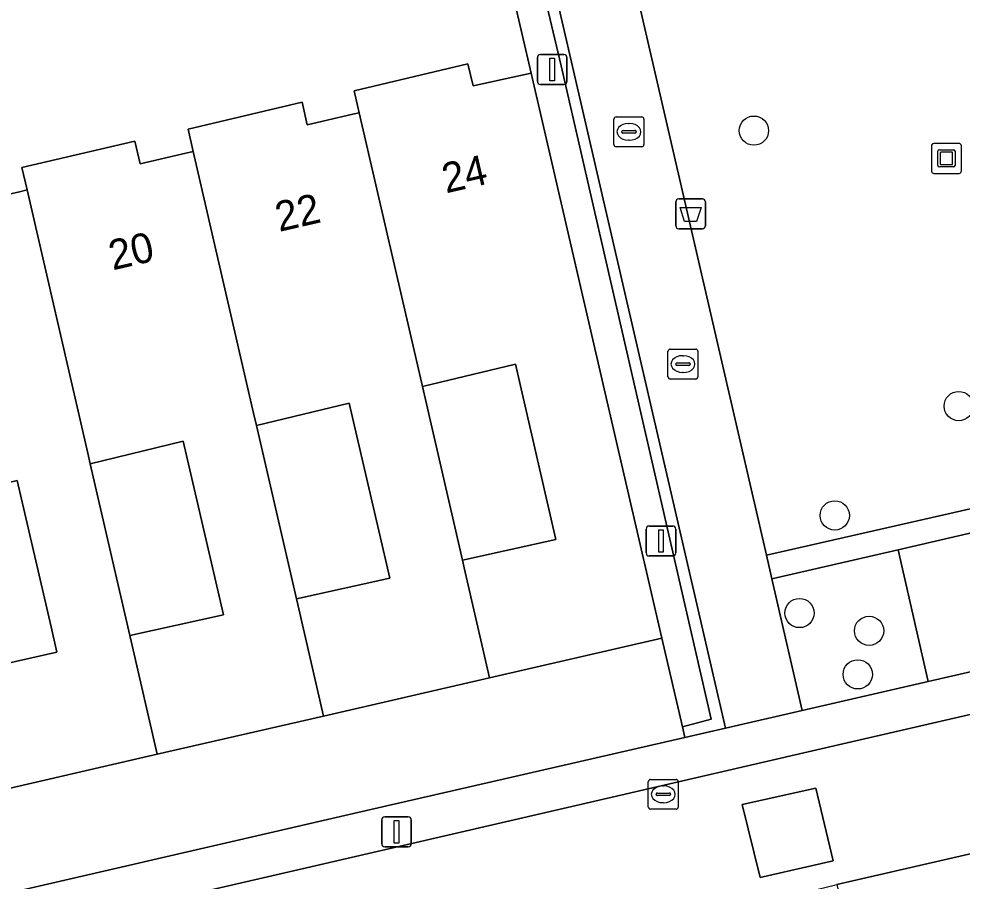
# Model space of a CAD drawing. Extents: x 156412 to 157779, y 382335 to 383768.
# Drawn here: x 156778.51 to 156810.03, y 382711.6 to 382740.43 of the extents above; entities that cross this region are included whole.
import ezdxf

# ---------------------------------------------------------------- set-up
doc = ezdxf.new("R2010")
doc.units = 0
for name, color, linetype in [('IMGEO_Afvalbak', 7, 'Continuous'), ('IMGEO_Boom', 7, 'Continuous'), ('IMGEO_Erf', 7, 'Continuous'), ('IMGEO_Groenvoorziening', 7, 'Continuous'), ('IMGEO_Haag', 7, 'Continuous'), ('IMGEO_Kolk', 7, 'Continuous'), ('IMGEO_Kunstobject', 7, 'Continuous'), ('IMGEO_Lichtmast', 7, 'Continuous'), ('IMGEO_Muur', 7, 'Continuous'), ('IMGEO_Pand', 7, 'Continuous'), ('IMGEO_Pand_nummerreeks', 7, 'Continuous'), ('IMGEO_Parkeervlak_open', 7, 'Continuous'), ('IMGEO_Rijbaan_lokaal_open', 7, 'Continuous'), ('IMGEO_Voetpad_open', 7, 'Continuous')]:
    doc.layers.add(name, color=color, linetype=linetype)

msp = doc.modelspace()

# ---------------------------------------------------------------- linework, layer by layer
at = {"layer": 'IMGEO_Afvalbak'}
for p, q in [((156800.462, 382733.511), (156800.462, 382734.311)), ((156800.462, 382734.311), (156800.462, 382733.511)), ((156800.562, 382734.411), (156801.352, 382734.411)), ((156801.352, 382734.411), (156800.562, 382734.411)), ((156801.452, 382734.311), (156801.452, 382733.511)), ((156801.452, 382733.511), (156801.452, 382734.311)), ((156801.352, 382733.411), (156800.562, 382733.411)), ((156800.562, 382733.411), (156801.352, 382733.411))]:
    msp.add_line(p, q, dxfattribs=at)
msp.add_lwpolyline([(156800.605, 382734.125), (156801.309, 382734.125), (156801.16, 382733.655), (156800.754, 382733.655), (156800.605, 382734.125)], dxfattribs=at)
for centre, start, end in [((156800.562, 382734.311), 90, 180), ((156800.562, 382734.311), 90, 180), ((156801.352, 382734.311), 0, 90), ((156801.352, 382734.311), 360, 90), ((156800.562, 382733.511), 180, 270), ((156800.562, 382733.511), 180, 270), ((156801.352, 382733.511), 270, 0), ((156801.352, 382733.511), 270, 0)]:
    msp.add_arc(centre, 0.1, start, end, dxfattribs=at)
at = {"layer": 'IMGEO_Boom'}
for centre in [(156803.074, 382736.692), (156809.918, 382727.482), (156805.775, 382723.827), (156804.597, 382720.564), (156806.924, 382719.969), (156806.543, 382718.514)]:
    msp.add_circle(centre, 0.489, dxfattribs=at)
at = {"layer": 'IMGEO_Erf'}
for points in [[(156777.006, 382734.296), (156778.533, 382734.65), (156778.783, 382734.708), (156778.609, 382735.464), (156782.383, 382736.34), (156782.558, 382735.581), (156784.085, 382735.935), (156784.335, 382735.993), (156784.162, 382736.744), (156787.973, 382737.649), (156788.148, 382736.89), (156789.675, 382737.244), (156789.883, 382737.292), (156789.714, 382738.026), (156793.515, 382738.921), (156793.695, 382738.186), (156795.633, 382738.617), (156794.426, 382743.797)], [(156831.783, 382717.455), (156805.847, 382711.483), (156807.399, 382705.016), (156810.455, 382705.715)]]:
    msp.add_lwpolyline(points, dxfattribs=at)
for points in [[(156791.995, 382728.14), (156793.335, 382722.33), (156796.459, 382723.019), (156795.105, 382728.888)], [(156786.447, 382726.837), (156787.784, 382721.041), (156790.901, 382721.73), (156789.551, 382727.585)], [(156780.893, 382725.557), (156782.217, 382719.815), (156785.342, 382720.506), (156784.005, 382726.306)], [(156775.346, 382724.25), (156776.66, 382718.554), (156779.777, 382719.26), (156779.584, 382720.099), (156778.454, 382724.998)], [(156790.128, 382713.958), (156800.769, 382716.402), (156800.687, 382716.754), (156799.998, 382719.724), (156794.242, 382718.399), (156788.688, 382717.12), (156783.133, 382715.842), (156777.58, 382714.563), (156772.025, 382713.284), (156766.472, 382712.006), (156760.917, 382710.727), (156755.363, 382709.449), (156749.81, 382708.17), (156744.255, 382706.892), (156738.701, 382705.613), (156732.984, 382704.297), (156732.018, 382708.516), (156732.308, 382708.586), (156735.332, 382709.254), (156734.066, 382714.657), (156727.251, 382713.017), (156729.431, 382703.479), (156730.2, 382700.114)]]:
    msp.add_lwpolyline(points, close=True, dxfattribs=at)
at = {"layer": 'IMGEO_Groenvoorziening'}
for points in [[(156812.585, 382748.399), (156807.635, 382747.256), (156806.778, 382747.058), (156806.927, 382746.477), (156798.417, 382744.512), (156803.492, 382722.496), (156834.402, 382729.53)], [(156834.402, 382729.53), (156803.492, 382722.496), (156803.627, 382721.911), (156803.674, 382721.707), (156807.895, 382722.68), (156810.39, 382723.256)]]:
    msp.add_lwpolyline(points, dxfattribs=at)
msp.add_lwpolyline([(156800.687, 382716.754), (156801.644, 382717.012), (156796.63, 382738.862), (156795.403, 382744.032), (156794.426, 382743.797), (156795.633, 382738.617), (156799.998, 382719.724)], close=True, dxfattribs=at)
at = {"layer": 'IMGEO_Haag'}
msp.add_lwpolyline([(156834.402, 382729.53), (156803.492, 382722.496), (156803.627, 382721.911), (156803.674, 382721.707), (156807.895, 382722.68), (156810.39, 382723.256)], dxfattribs=at)
at = {"layer": 'IMGEO_Kolk'}
for p, q in [((156798.472, 382737.153), (156799.324, 382737.153)), ((156798.397, 382736.227), (156798.397, 382737.079)), ((156798.885, 382736.933), (156798.91, 382736.933)), ((156799.398, 382737.079), (156799.398, 382736.227)), ((156798.656, 382736.647), (156798.656, 382736.659)), ((156799.094, 382736.61), (156798.696, 382736.61)), ((156798.699, 382736.696), (156799.097, 382736.696)), ((156799.14, 382736.659), (156799.14, 382736.647)), ((156799.324, 382736.153), (156798.472, 382736.153)), ((156798.908, 382736.373), (156798.883, 382736.373)), ((156800.202, 382728.462), (156800.202, 382729.314)), ((156800.277, 382729.388), (156801.129, 382729.388)), ((156801.203, 382729.314), (156801.203, 382728.462)), ((156800.504, 382728.931), (156800.902, 382728.931)), ((156800.69, 382729.168), (156800.715, 382729.168)), ((156800.461, 382728.882), (156800.461, 382728.894)), ((156800.899, 382728.845), (156800.501, 382728.845)), ((156800.713, 382728.608), (156800.688, 382728.608)), ((156800.945, 382728.894), (156800.945, 382728.882)), ((156801.129, 382728.388), (156800.277, 382728.388)), ((156799.545, 382714.077), (156799.545, 382714.929)), ((156799.62, 382715.003), (156800.472, 382715.003)), ((156800.033, 382714.783), (156800.058, 382714.783)), ((156800.546, 382714.929), (156800.546, 382714.077)), ((156799.804, 382714.497), (156799.804, 382714.509)), ((156800.242, 382714.46), (156799.844, 382714.46)), ((156799.847, 382714.546), (156800.245, 382714.546)), ((156800.288, 382714.509), (156800.288, 382714.497)), ((156800.056, 382714.223), (156800.031, 382714.223)), ((156800.472, 382714.003), (156799.62, 382714.003))]:
    msp.add_line(p, q, dxfattribs=at)
for points in [[(156798.472, 382737.153), (156799.324, 382737.153)], [(156798.397, 382736.227), (156798.397, 382737.079)], [(156799.398, 382737.079), (156799.398, 382736.227)], [(156799.324, 382736.153), (156798.472, 382736.153)], [(156800.202, 382728.462), (156800.202, 382729.314)], [(156800.277, 382729.388), (156801.129, 382729.388)], [(156801.203, 382729.314), (156801.203, 382728.462)], [(156801.129, 382728.388), (156800.277, 382728.388)], [(156799.545, 382714.077), (156799.545, 382714.929)], [(156799.62, 382715.003), (156800.472, 382715.003)], [(156800.546, 382714.929), (156800.546, 382714.077)], [(156800.472, 382714.003), (156799.62, 382714.003)]]:
    msp.add_lwpolyline(points, dxfattribs=at)
for centre, radius, start, end in [((156798.474, 382737.077), 0.0765, 91.552, 178.448), ((156798.474, 382737.077), 0.0765, 91.552, 178.448), ((156799.322, 382737.077), 0.0765, 1.552, 88.448), ((156799.322, 382737.077), 0.0765, 1.552, 88.448), ((156798.696, 382736.656), 0.0403, 85.8775, 175.7526), ((156798.693, 382736.646), 0.0366, 178.938, 274.7102), ((156799.097, 382736.653), 0.043, 264.8664, 352.4533), ((156799.101, 382736.658), 0.0386, 1.7309, 96.639), ((156798.474, 382736.229), 0.0765, 181.552, 268.448), ((156798.474, 382736.229), 0.0765, 181.552, 268.448), ((156799.322, 382736.229), 0.0765, 271.552, 358.448), ((156799.322, 382736.229), 0.0765, 271.552, 358.448), ((156800.279, 382729.312), 0.0765, 91.552, 178.448), ((156800.279, 382729.312), 0.0765, 91.552, 178.448), ((156801.127, 382729.312), 0.0765, 1.552, 88.448), ((156801.127, 382729.312), 0.0765, 1.552, 88.448), ((156800.501, 382728.891), 0.0403, 85.8775, 175.7526), ((156800.906, 382728.893), 0.0386, 1.7309, 96.639), ((156800.498, 382728.881), 0.0366, 178.938, 274.7102), ((156800.902, 382728.888), 0.043, 264.8664, 352.4533), ((156800.279, 382728.464), 0.0765, 181.552, 268.448), ((156800.279, 382728.464), 0.0765, 181.552, 268.448), ((156801.127, 382728.464), 0.0765, 271.552, 358.448), ((156801.127, 382728.464), 0.0765, 271.552, 358.448), ((156799.622, 382714.927), 0.0765, 91.552, 178.448), ((156799.622, 382714.927), 0.0765, 91.552, 178.448), ((156800.47, 382714.927), 0.0765, 1.552, 88.448), ((156800.47, 382714.927), 0.0765, 1.552, 88.448), ((156799.844, 382714.506), 0.0403, 85.8775, 175.7526), ((156799.841, 382714.496), 0.0366, 178.938, 274.7102), ((156800.245, 382714.503), 0.043, 264.8664, 352.4533), ((156800.249, 382714.508), 0.0386, 1.7309, 96.639), ((156799.622, 382714.079), 0.0765, 181.552, 268.448), ((156799.622, 382714.079), 0.0765, 181.552, 268.448), ((156800.47, 382714.079), 0.0765, 271.552, 358.448), ((156800.47, 382714.079), 0.0765, 271.552, 358.448)]:
    msp.add_arc(centre, radius, start, end, dxfattribs=at)
for centre, major_axis, ratio, start_param, end_param in [((156798.884, 382736.653), (-0.387, 0.002), 0.722429, 4.712389, 7.853982), ((156798.909, 382736.653), (-0.39, 0.002), 0.717154, 1.570796, 4.712389), ((156800.689, 382728.888), (-0.387, 0.002), 0.722429, 4.712389, 7.853982), ((156800.714, 382728.888), (-0.39, 0.002), 0.717154, 1.570796, 4.712389), ((156800.032, 382714.503), (-0.387, 0.002), 0.722429, 4.712389, 7.853982), ((156800.057, 382714.503), (-0.39, 0.002), 0.717154, 1.570796, 4.712389)]:
    msp.add_ellipse(centre, major_axis=major_axis, ratio=ratio, start_param=start_param, end_param=end_param, dxfattribs=at)
at = {"layer": 'IMGEO_Kunstobject'}
for p, q in [((156809.007, 382736.18), (156809.007, 382735.339)), ((156809.007, 382736.18), (156809.007, 382735.339)), ((156809.923, 382736.264), (156809.082, 382736.264)), ((156809.923, 382736.264), (156809.082, 382736.264)), ((156810.007, 382735.348), (156810.007, 382736.189)), ((156810.007, 382735.348), (156810.007, 382736.189)), ((156809.221, 382735.528), (156809.221, 382736.002)), ((156809.271, 382736.052), (156809.745, 382736.052)), ((156809.301, 382735.952), (156809.301, 382735.578)), ((156809.695, 382735.972), (156809.321, 382735.972)), ((156809.715, 382735.578), (156809.715, 382735.952)), ((156809.795, 382736.002), (156809.795, 382735.528)), ((156809.321, 382735.558), (156809.695, 382735.558)), ((156809.091, 382735.264), (156809.932, 382735.264)), ((156809.091, 382735.264), (156809.932, 382735.264)), ((156809.745, 382735.478), (156809.271, 382735.478))]:
    msp.add_line(p, q, dxfattribs=at)
for centre, radius, start, end in [((156809.085, 382736.186), 0.0779, 92.4484, 184.2845), ((156809.085, 382736.186), 0.0779, 92.4484, 184.2845), ((156809.929, 382736.186), 0.0779, 2.4484, 94.2845), ((156809.929, 382736.186), 0.0779, 2.4484, 94.2845), ((156809.271, 382736.002), 0.05, 90, 180), ((156809.321, 382735.952), 0.02, 90, 180), ((156809.695, 382735.952), 0.02, 360, 90), ((156809.745, 382736.002), 0.05, 360, 90), ((156809.271, 382735.528), 0.05, 180, 270), ((156809.321, 382735.578), 0.02, 180, 270), ((156809.695, 382735.578), 0.02, 270, 0), ((156809.745, 382735.528), 0.05, 270, 0), ((156809.085, 382735.342), 0.0779, 182.4484, 274.2845), ((156809.085, 382735.342), 0.0779, 182.4484, 274.2845), ((156809.929, 382735.342), 0.0779, 272.4484, 4.2845), ((156809.929, 382735.342), 0.0779, 272.4484, 4.2845)]:
    msp.add_arc(centre, radius, start, end, dxfattribs=at)
at = {"layer": 'IMGEO_Lichtmast'}
for p, q in [((156795.836, 382738.338), (156795.836, 382739.138)), ((156795.836, 382739.138), (156795.836, 382738.338)), ((156795.936, 382739.238), (156796.726, 382739.238)), ((156796.726, 382739.238), (156795.936, 382739.238)), ((156796.826, 382739.138), (156796.826, 382738.338)), ((156796.826, 382738.338), (156796.826, 382739.138)), ((156796.726, 382738.238), (156795.936, 382738.238)), ((156795.936, 382738.238), (156796.726, 382738.238)), ((156799.471, 382722.571), (156799.471, 382723.371)), ((156799.471, 382723.371), (156799.471, 382722.571)), ((156799.571, 382723.471), (156800.361, 382723.471)), ((156800.361, 382723.471), (156799.571, 382723.471)), ((156800.461, 382723.371), (156800.461, 382722.571)), ((156800.461, 382722.571), (156800.461, 382723.371)), ((156800.361, 382722.471), (156799.571, 382722.471)), ((156799.571, 382722.471), (156800.361, 382722.471)), ((156790.634, 382712.849), (156790.634, 382713.649)), ((156790.634, 382713.649), (156790.634, 382712.849)), ((156790.734, 382713.749), (156791.524, 382713.749)), ((156791.524, 382713.749), (156790.734, 382713.749)), ((156791.624, 382713.649), (156791.624, 382712.849)), ((156791.624, 382712.849), (156791.624, 382713.649)), ((156791.524, 382712.749), (156790.734, 382712.749)), ((156790.734, 382712.749), (156791.524, 382712.749))]:
    msp.add_line(p, q, dxfattribs=at)
for points in [[(156796.256, 382739.113), (156796.406, 382739.113), (156796.406, 382738.363), (156796.256, 382738.363), (156796.256, 382739.113)], [(156799.891, 382723.346), (156800.041, 382723.346), (156800.041, 382722.596), (156799.891, 382722.596), (156799.891, 382723.346)], [(156791.054, 382713.624), (156791.204, 382713.624), (156791.204, 382712.874), (156791.054, 382712.874), (156791.054, 382713.624)]]:
    msp.add_lwpolyline(points, dxfattribs=at)
for centre, start, end in [((156795.936, 382739.138), 90, 180), ((156795.936, 382739.138), 90, 180), ((156796.726, 382739.138), 0, 90), ((156796.726, 382739.138), 360, 90), ((156795.936, 382738.338), 180, 270), ((156795.936, 382738.338), 180, 270), ((156796.726, 382738.338), 270, 0), ((156796.726, 382738.338), 270, 0), ((156799.571, 382723.371), 90, 180), ((156799.571, 382723.371), 90, 180), ((156800.361, 382723.371), 0, 90), ((156800.361, 382723.371), 360, 90), ((156799.571, 382722.571), 180, 270), ((156799.571, 382722.571), 180, 270), ((156800.361, 382722.571), 270, 0), ((156800.361, 382722.571), 270, 0), ((156790.734, 382713.649), 90, 180), ((156790.734, 382713.649), 90, 180), ((156791.524, 382713.649), 0, 90), ((156791.524, 382713.649), 360, 90), ((156790.734, 382712.849), 180, 270), ((156790.734, 382712.849), 180, 270), ((156791.524, 382712.849), 270, 0), ((156791.524, 382712.849), 270, 0)]:
    msp.add_arc(centre, 0.1, start, end, dxfattribs=at)
at = {"layer": 'IMGEO_Muur'}
msp.add_lwpolyline([(156795.712, 382744.485), (156794.348, 382744.171), (156794.426, 382743.797), (156795.403, 382744.032), (156796.63, 382738.862), (156801.644, 382717.012), (156800.687, 382716.754), (156800.769, 382716.402), (156802.123, 382716.713)], close=True, dxfattribs=at)
at = {"layer": 'IMGEO_Pand'}
for points in [[(156795.633, 382738.617), (156793.695, 382738.186), (156793.515, 382738.921), (156789.714, 382738.026), (156789.883, 382737.292), (156791.894, 382728.574), (156791.995, 382728.14), (156795.105, 382728.888), (156796.459, 382723.019), (156793.335, 382722.33), (156793.394, 382722.076), (156794.242, 382718.399), (156799.998, 382719.724)], [(156791.995, 382728.14), (156791.894, 382728.574), (156789.883, 382737.292), (156789.675, 382737.244), (156788.148, 382736.89), (156787.973, 382737.649), (156784.162, 382736.744), (156784.335, 382735.993), (156786.354, 382727.241), (156786.447, 382726.837), (156789.551, 382727.585), (156790.901, 382721.73), (156787.784, 382721.041), (156787.828, 382720.847), (156788.688, 382717.12), (156794.242, 382718.399), (156793.394, 382722.076), (156793.335, 382722.33)], [(156786.447, 382726.837), (156786.354, 382727.241), (156784.335, 382735.993), (156784.085, 382735.935), (156782.558, 382735.581), (156782.383, 382736.34), (156778.609, 382735.464), (156778.783, 382734.708), (156780.812, 382725.907), (156780.893, 382725.557), (156784.005, 382726.306), (156785.342, 382720.506), (156782.217, 382719.815), (156782.262, 382719.618), (156783.133, 382715.842), (156788.688, 382717.12), (156787.828, 382720.847), (156787.784, 382721.041)], [(156780.893, 382725.557), (156780.812, 382725.907), (156778.783, 382734.708), (156778.533, 382734.65), (156777.006, 382734.296), (156776.831, 382735.055), (156773.056, 382734.182), (156773.229, 382733.431), (156775.272, 382724.574), (156775.346, 382724.25), (156778.454, 382724.998), (156779.584, 382720.099), (156779.777, 382719.26), (156776.66, 382718.554), (156776.698, 382718.39), (156777.58, 382714.563), (156783.133, 382715.842), (156782.262, 382719.618), (156782.217, 382719.815)]]:
    msp.add_lwpolyline(points, close=True, dxfattribs=at)
at = {"layer": 'IMGEO_Parkeervlak_open'}
msp.add_lwpolyline([(156810.39, 382723.256), (156807.895, 382722.68), (156808.902, 382718.276), (156811.426, 382718.859)], close=True, dxfattribs=at)
at = {"layer": 'IMGEO_Rijbaan_lokaal_open'}
for points in [[(156954.997, 382755.422), (156950.885, 382751.332), (156949.815, 382749.383), (156929.495, 382744.678), (156907.413, 382739.578), (156879.275, 382733.088), (156868.803, 382730.665), (156830.401, 382721.812), (156805.031, 382715.955), (156791.204, 382712.755), (156730.522, 382698.738), (156728.301, 382699.143), (156722.872, 382699.769)], [(156725.3, 382689.329), (156729.8, 382692.978), (156731.555, 382694.305), (156790.393, 382707.765), (156801.982, 382710.553), (156804.578, 382711.178), (156804.954, 382711.268), (156805.847, 382711.483), (156831.783, 382717.455), (156841.152, 382719.616), (156876.422, 382727.751)]]:
    msp.add_lwpolyline(points, dxfattribs=at)
for points in [[(156803.281, 382711.716), (156805.717, 382712.279), (156805.139, 382714.707), (156802.681, 382714.158)], [(156805.717, 382712.279), (156803.281, 382711.716), (156802.681, 382714.158), (156805.139, 382714.707)]]:
    msp.add_lwpolyline(points, close=True, dxfattribs=at)
at = {"layer": 'IMGEO_Voetpad_open'}
for points in [[(156798.417, 382744.512), (156798.332, 382744.878), (156798.282, 382745.097), (156795.712, 382744.485), (156802.123, 382716.713), (156804.689, 382717.303), (156803.674, 382721.707), (156803.627, 382721.911), (156803.492, 382722.496)], [(156807.895, 382722.68), (156803.674, 382721.707), (156804.689, 382717.303), (156808.902, 382718.276)]]:
    msp.add_lwpolyline(points, close=True, dxfattribs=at)
msp.add_lwpolyline([(156811.426, 382718.859), (156808.902, 382718.276), (156804.689, 382717.303), (156802.123, 382716.713), (156800.769, 382716.402), (156790.128, 382713.958), (156730.2, 382700.114), (156730.522, 382698.738), (156791.204, 382712.755), (156805.031, 382715.955), (156830.401, 382721.812)], dxfattribs=at)

# ---------------------------------------------------------------- texts
at = {"layer": 'IMGEO_Pand_nummerreeks'}
for s, p in [('24', (156792.782, 382734.592)), ('22', (156787.208, 382733.304)), ('20', (156781.644, 382732.018))]:
    msp.add_text(s, height=1, rotation=13.0119, dxfattribs=at).set_placement(p)

doc.saveas('drawing.dxf')
